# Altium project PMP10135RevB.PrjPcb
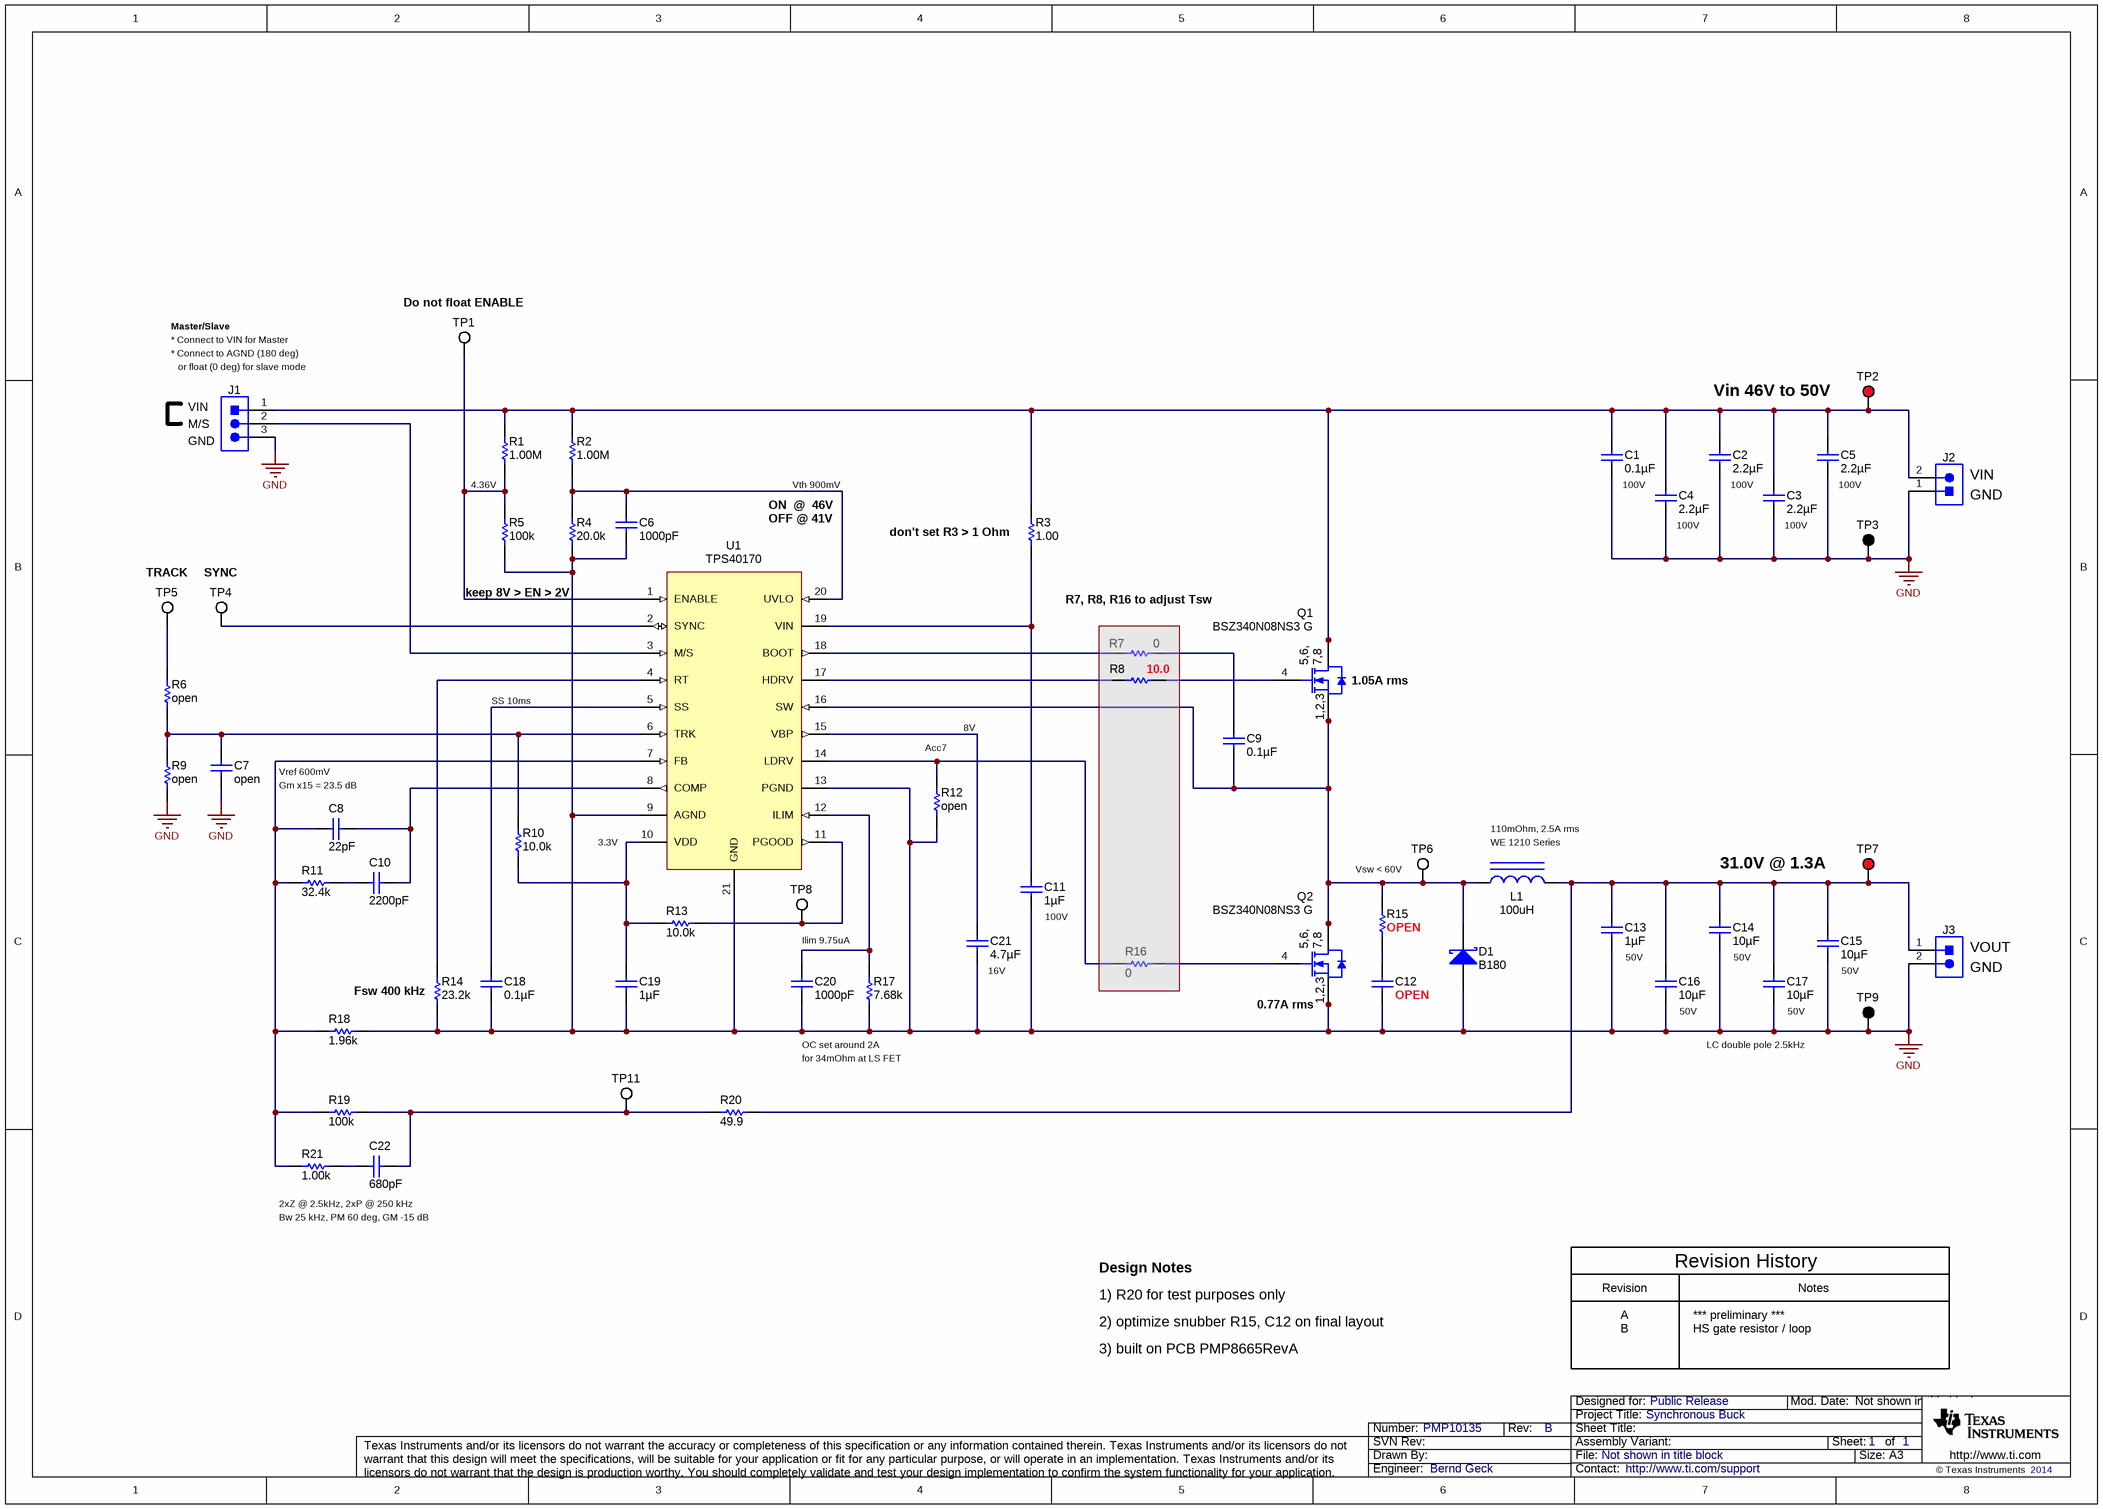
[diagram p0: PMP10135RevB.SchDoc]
CopyrightYear: 2014; PCB_Layout: B. Geck; PCB_Rev: A; PRJ_Customer: Public Release; PRJ_Engineer: Bernd Geck; PRJ_Number: PMP10135; PRJ_Title: Synchronous Buck; SCH_Rev: B; TechSupport: http://www.ti.com/support
1 sheet, 61 parts. Net scope: global (net labels, ports and power ports of the same name join across sheets).

## Sheet PMP10135RevB.SchDoc
size A3; Date: Not shown in title block; ApprovedBy: Not shown in title block; CheckedBy: Not shown in title block; Author: Not shown in title block; CompanyName: Not shown in title block; Engineer: Not shown in title block; Organization: Not shown in title block; Address1: Not shown in title block; Address2: Not shown in title block; Address3: Not shown in title block; Address4: Not shown in title block; DocumentNumber: 1; Revision: Use project parameter SCH_Rev; SheetNumber: 1; SheetTotal: 1; PageSetup: Record=PageOptions|CenterHorizontal=True|CenterVertical=True|PrintScale=0.97|XCorrection=1.00|YCorrection=1.00|PrintKind=0|BorderSize=5000000|LeftOffset=0|BottomOffset=0|Orientation=2|PaperLength=1000|PaperWidth=1000|Scale=100|PaperSource=15|PrintQuality=600|MediaType=1|DitherType=10|PaperKind=A4|PrintScaleMode=1

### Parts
C1  ValueDisplayed: 0.1µF  Value2: 100V  [0805_HV]  (hidden comment: C2012X7R2A104K)
C2  ValueDisplayed: 2.2µF  Value2: 100V  [1210]  (hidden comment: GRM32ER72A225KA35L)
C3  ValueDisplayed: 2.2µF  Value2: 100V  [1210]  (hidden comment: GRM32ER72A225KA35L)
C4  ValueDisplayed: 2.2µF  Value2: 100V  [1210]  (hidden comment: GRM32ER72A225KA35L)
C5  ValueDisplayed: 2.2µF  Value2: 100V  [1210]  (hidden comment: GRM32ER72A225KA35L)
C6  ValueDisplayed: 1000pF  [0402]  (hidden comment: GRM155R71H102KA01D)
C7  ValueDisplayed: open  [0402]  (hidden comment: GRM1535C1H101JDD5D)
C8  ValueDisplayed: 22pF  [0402]  (hidden comment: GRM1555C1H220JA01D)
C9  ValueDisplayed: 0.1µF  [0603]  (hidden comment: GRM188R71H104KA93D)
C10  ValueDisplayed: 2200pF  [0402]  (hidden comment: GRM155R71E222KA01D)
C11  ValueDisplayed: 1µF  Value2: 100V  [1206]  (hidden comment: GRM31CR72A105KA01L)
C12  ValueDisplayed: OPEN  [0805_HV]  (hidden comment: C2012X7R2A102K)
C13  ValueDisplayed: 1µF  Value2: 50V  [0805_HV]  (hidden comment: GRM21BR71H105KA12L)
C14  ValueDisplayed: 10µF  Value2: 50V  [1210]  (hidden comment: GRM32ER71H106KA12L)
C15  ValueDisplayed: 10µF  Value2: 50V  [1210]  (hidden comment: GRM32ER71H106KA12L)
C16  ValueDisplayed: 10µF  Value2: 50V  [1210]  (hidden comment: GRM32ER71H106KA12L)
C17  ValueDisplayed: 10µF  Value2: 50V  [1210]  (hidden comment: GRM32ER71H106KA12L)
C18  ValueDisplayed: 0.1µF  [0603]  (hidden comment: GRM188R71H104KA93D)
C19  ValueDisplayed: 1µF  [0603]  (hidden comment: GRM188R71E105KA12D)
C20  ValueDisplayed: 1000pF  [0603]  (hidden comment: GRM188R71H102KA01D)
C21  ValueDisplayed: 4.7µF  Value2: 16V  [0805_HV]  (hidden comment: GRM21BR71C475KA73L)
C22  ValueDisplayed: 680pF  [0402]  (hidden comment: GRM155R71H681KA01D)
D1  B180  [SMA]
J1  PEC03SAAN  [CONN_PEC03SAAN]  (value not drawn)
J2  ED555/2DS  [TERM_BLK_ED555-2DS]  (value not drawn)
J3  ED555/2DS  [TERM_BLK_ED555-2DS]  (value not drawn)
L1  100uH  [WE-PD-XXL]
Q1  BSZ340N08NS3 G  [PG-TSDSON-8]
Q2  BSZ340N08NS3 G  [PG-TSDSON-8]
R1  ValueDisplayed: 1.00M  [0805_HV]  (hidden comment: CRCW08051M00FKEA)
R2  ValueDisplayed: 1.00M  [0805_HV]  (hidden comment: CRCW08051M00FKEA)
R3  ValueDisplayed: 1.00  [0805_HV]  (hidden comment: CRCW08051R00FKEA)
R4  ValueDisplayed: 20.0k  [0402]  (hidden comment: CRCW040220K0FKED)
R5  ValueDisplayed: 100k  [0402]  (hidden comment: CRCW0402100KFKED)
R6  ValueDisplayed: open  [0402]  (hidden comment: CRCW040210K0FKED)
R7  ValueDisplayed: 0  [0603]  (hidden comment: CRCW06030000Z0EA)
R8  ValueDisplayed: 10.0  [0402]  (hidden comment: CRCW040210R0FKED)
R9  ValueDisplayed: open  [0402]  (hidden comment: CRCW040210K0FKED)
R10  ValueDisplayed: 10.0k  [0603]  (hidden comment: CRCW060310K0FKEA)
R11  ValueDisplayed: 32.4k  [0402]  (hidden comment: CRCW040232K4FKED)
R12  ValueDisplayed: open  [0603]  (hidden comment: CRCW060310K0FKEA)
R13  ValueDisplayed: 10.0k  [0603]  (hidden comment: CRCW060310K0FKEA)
R14  ValueDisplayed: 23.2k  [0402]  (hidden comment: CRCW040223K2FKED)
R15  ValueDisplayed: OPEN  [1206]  (hidden comment: CRCW120622R0JNEA)
R16  ValueDisplayed: 0  [0603]  (hidden comment: CRCW06030000Z0EA)
R17  ValueDisplayed: 7.68k  [0603]  (hidden comment: CRCW06037K68FKEA)
R18  ValueDisplayed: 1.96k  [0603]  (hidden comment: CRCW06031K96FKEA)
R19  ValueDisplayed: 100k  [0402]  (hidden comment: CRCW0402100KFKED)
R20  ValueDisplayed: 49.9  [0603]  (hidden comment: CRCW060349R9FKEA)
R21  ValueDisplayed: 1.00k  [0402]  (hidden comment: CRCW04021K00FKED)
TP1  5002  [Keystone5002]  (value not drawn)
TP2  5000  [Keystone5000]  (value not drawn)
TP3  5001  [Keystone5001]  (value not drawn)
TP4  5002  [Keystone5002]  (value not drawn)
TP5  5002  [Keystone5002]  (value not drawn)
TP6  5002  [Keystone5002]  (value not drawn)
TP7  5000  [Keystone5000]  (value not drawn)
TP8  5002  [Keystone5002]  (value not drawn)
TP9  5001  [Keystone5001]  (value not drawn)
TP11  5002  [Keystone5002]  (value not drawn)
U1  TPS40170  [RGY0020A]

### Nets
GND: C1.2 C2.2 C3.2 C4.2 C5.2 C6.2 C7.2 C11.2 C12.2 C13.2 C14.2 C15.2 C16.2 C17.2 C18.2 C19.2 C20.2 C21.2 D1.2(A) J1.3 J2.1 J3.2 Q2.1(S) Q2.2(S) Q2.3(S) R4.1 R5.1 R9.1 R12.1 R14.1 R17.1 R18.2 TP3.1 TP9.1 U1.9(AGND) U1.13(PGND) U1.21(GND)
NetC1_1: C1.1 C2.1 C3.1 C4.1 C5.1 J1.1 J2.2 Q1.5(D) Q1.6(D) Q1.7(D) Q1.8(D) Q1.9(D) R1.2 R2.2 R3.2 TP2.1
NetC6_1: C6.1 R2.1 R4.2 U1.20(UVLO)
NetC7_1: C7.1 R6.1 R9.2 R10.2 U1.6(TRK)
NetC8_1: C8.1 C10.1 U1.8(COMP)
NetC8_2: C8.2 R11.1 R18.1 R19.1 R21.1 U1.7(FB)
NetC9_1: C9.1 R7.2
NetC9_2: C9.2 D1.1(K) L1.1 Q1.1(S) Q1.2(S) Q1.3(S) Q2.5(D) Q2.6(D) Q2.7(D) Q2.8(D) Q2.9(D) R15.2 TP6.1 U1.16(SW)
NetC10_2: C10.2 R11.2
NetC11_1: C11.1 R3.1 U1.19(VIN)
NetC12_1: C12.1 R15.1
NetC13_1: C13.1 C14.1 C15.1 C16.1 C17.1 J3.1 L1.2 R20.2 TP7.1
NetC18_1: C18.1 U1.5(SS)
NetC19_1: C19.1 R10.1 R13.1 U1.10(VDD)
NetC20_1: C20.1 R17.2 U1.12(ILIM)
NetC21_1: C21.1 U1.15(VBP)
NetC22_1: C22.1 R19.2 R20.1 TP11.1
NetC22_2: C22.2 R21.2
NetJ1_2: J1.2 U1.3(M/S)
NetQ1_4: Q1.4(G) R8.2
NetQ2_4: Q2.4(G) R16.2
NetR1_1: R1.1 R5.2 TP1.1 U1.1(ENABLE)
NetR6_2: R6.2 TP5.1
NetR7_1: R7.1 U1.18(BOOT)
NetR8_1: R8.1 U1.17(HDRV)
NetR12_2: R12.2 R16.1 U1.14(LDRV)
NetR13_2: R13.2 TP8.1 U1.11(PGOOD)
NetR14_2: R14.2 U1.4(RT)
NetTP4_1: TP4.1 U1.2(SYNC)

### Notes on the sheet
- (near TP1) Do not float ENABLE
- Master/Slave
- * Connect to VIN for Master
- (near J1) * Connect to AGND (180 deg)
- (near J1) or float (0 deg) for slave mode
- (near J1) M/S
- (near J1) GND
- (near J1) VIN
- Vin 46V to 50V
- (near R1) 4.36V
- ON  @  46V
- OFF @ 41V
- Vth 900mV
- (near J2) VIN
- (near J2) GND
- TRACK
- SYNC
- keep 8V > EN > 2V
- (near R3) don't set R3 > 1 Ohm
- R7, R8, R16 to adjust Tsw
- SS 10ms
- 8V
- (near Q1) 1.05A rms
- Vref 600mV
- Gm x15 = 23.5 dB
- (near R12) Acc7
- (near U1) 3.3V
- (near L1) WE 1210 Series
- 110mOhm, 2.5A rms
- 31.0V @ 1.3A
- Vsw < 60V
- (near R14) Fsw 400 kHz
- Ilim 9.75uA
- (near J3) VOUT
- (near J3) GND
- OC set around 2A
- for 34mOhm at LS FET
- (near Q2) 0.77A rms
- LC double pole 2.5kHz
- 2xZ @ 2.5kHz, 2xP @ 250 kHz
- Bw 25 kHz, PM 60 deg, GM -15 dB
- Design Notes
- Revision History
- 1) R20 for test purposes only
- 2) optimize snubber R15, C12 on final layout
- Revision
- A
- B
- *** preliminary ***
- HS gate resistor / loop
- Notes
- 3) built on PCB PMP8665RevA

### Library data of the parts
C1 = C2012X7R2A104K: CAP, CERM, 0.1 µF, 100 V, +/- 10%, X7R, 0805; Manufacturer: TDK; Polarized: N; CompType: Capacitor; Value: 0.1uF; U/M: EA; Cap_F: 0.0000001; Tolerance_%: 10; ESR_ohm: 0.0158; Value1: 0.0158 ohm; VDC_V: 100; TaMin_C: -55; TaMax_C: 125; Cap_Case: 0805
C2-C5 = GRM32ER72A225KA35L: CAP, CERM, 2.2 µF, 100 V, +/- 10%, X7R, 1210; Manufacturer: MuRata; Polarized: N; CompType: Capacitor; Value: 2.2uF; U/M: EA; Cap_F: 0.0000022; Tolerance_%: 10; ESR_ohm: 0.007; Value1: 0.007 ohm; VDC_V: 100; IRMS_A: 4.4; TaMin_C: -55; TaMax_C: 125
C6 = GRM155R71H102KA01D: CAP, CERM, 1000 pF, 50 V, +/- 10%, X7R, 0402; Manufacturer: MuRata; Polarized: N; CompType: Capacitor; Value: 1000pF; U/M: EA; Cap_F: 0.000000001; Tolerance_%: 10; Value1: Unknown; VDC_V: 50; Value2: 50V; TaMin_C: -55; TaMax_C: 125
C7 = GRM1535C1H101JDD5D: CAP, CERM, 100 pF, 50 V, +/- 5%, C0G/NP0, 0402; Manufacturer: MuRata; Polarized: N; CompType: Capacitor; Value: 100pF; U/M: EA; Cap_F: 0.0000000001; Tolerance_%: 5; Value1: Unknown; VDC_V: 50; Value2: 50V; TaMin_C: -55; TaMax_C: 125
C8 = GRM1555C1H220JA01D: CAP, CERM, 22 pF, 50 V, +/- 5%, C0G/NP0, 0402; Manufacturer: MuRata; Polarized: N; CompType: Capacitor; Value: 22pF; U/M: EA; Cap_F: 0.000000000022; Tolerance_%: 5; Value1: Unknown; VDC_V: 50; Value2: 50V; TaMin_C: -55; TaMax_C: 125
C9 C18 = GRM188R71H104KA93D: CAP, CERM, 0.1 µF, 50 V, +/- 10%, X7R, 0603; Manufacturer: MuRata; Polarized: N; CompType: Capacitor; Value: 0.1uF; U/M: EA; Cap_F: 0.0000001; Tolerance_%: 10; Value1: Unknown; VDC_V: 50; Value2: 50V; TaMin_C: -55; TaMax_C: 125
C10 = GRM155R71E222KA01D: CAP, CERM, 2200 pF, 25 V, +/- 10%, X7R, 0402; Manufacturer: MuRata; Polarized: N; CompType: Capacitor; Value: 2200pF; U/M: EA; Cap_F: 0.0000000022; Tolerance_%: 10; Value1: Unknown; VDC_V: 25; Value2: 25V; TaMin_C: -55; TaMax_C: 125
C11 = GRM31CR72A105KA01L: CAP, CERM, 1 µF, 100 V, +/- 10%, X7R, 1206; Manufacturer: MuRata; Polarized: N; CompType: Capacitor; Value: 1uF; U/M: EA; Cap_F: 0.000001; Tolerance_%: 10; Value1: Unknown; VDC_V: 100; TaMin_C: -55; TaMax_C: 125; Cap_Case: 2220
C12 = C2012X7R2A102K: CAP, CERM, 1000 pF, 100 V, +/- 10%, X7R, 0805; Manufacturer: TDK; Polarized: N; CompType: Capacitor; Value: 1000pF; U/M: EA; Cap_F: 0.000000001; Tolerance_%: 10; ESR_ohm: 0.281; Value1: 0.281 ohm; VDC_V: 100; Value2: 100V; TaMin_C: -55; TaMax_C: 125; Cap_Case: 0805
C13 = GRM21BR71H105KA12L: CAP, CERM, 1 µF, 50 V, +/- 10%, X7R, 0805; Manufacturer: MuRata; Polarized: N; CompType: Capacitor; Value: 1uF; U/M: EA; Cap_F: 0.000001; Tolerance_%: 10; Value1: Unknown; VDC_V: 50; TaMin_C: -55; TaMax_C: 125; Cap_Case: 0805
C14-C17 = GRM32ER71H106KA12L: CAP, CERM, 10 µF, 50 V, +/- 10%, X7R, 1210; Manufacturer: MuRata; Polarized: N; CompType: Capacitor; Value: 10uF; U/M: EA; Cap_F: 0.00001; Tolerance_%: 10; Value1: Unknown; VDC_V: 50; TaMin_C: -55; TaMax_C: 125
C19 = GRM188R71E105KA12D: CAP, CERM, 1 µF, 25 V, +/- 10%, X7R, 0603; Manufacturer: MuRata; Polarized: N; CompType: Capacitor; Value: 1uF; U/M: EA; Cap_F: 0.000001; Tolerance_%: 10; Value1: Unknown; VDC_V: 25; Value2: 25V; TaMin_C: -55; TaMax_C: 125
C20 = GRM188R71H102KA01D: CAP, CERM, 1000 pF, 50 V, +/- 10%, X7R, 0603; Manufacturer: MuRata; Polarized: N; CompType: Capacitor; Value: 1000pF; U/M: EA; Cap_F: 0.000000001; Tolerance_%: 10; Value1: Unknown; VDC_V: 50; Value2: 50V; TaMin_C: -55; TaMax_C: 125
C21 = GRM21BR71C475KA73L: CAP, CERM, 4.7 µF, 16 V, +/- 10%, X7R, 0805; Manufacturer: MuRata; Polarized: N; CompType: Capacitor; Value: 4.7uF; U/M: EA; Cap_F: 0.0000047; Tolerance_%: 10; ESR_ohm: 0.006; Value1: 0.006 ohm; VDC_V: 16; TaMin_C: -55; TaMax_C: 125; Cap_Case: 0805
C22 = GRM155R71H681KA01D: CAP, CERM, 680 pF, 50 V, +/- 10%, X7R, 0402; Manufacturer: MuRata; Polarized: N; CompType: Capacitor; Value: 680pF; U/M: EA; Cap_F: 0.00000000068; Tolerance_%: 10; Value1: Unknown; VDC_V: 50; Value2: 50V; TaMin_C: -55; TaMax_C: 125
D1 = B180-13-F: Diode, Schottky, 80 V, 1 A, SMA; Manufacturer: Diodes Inc.; U/M: EA; Vf_V: 0.79; Value: 80V; Value1: 1A; Value2: 0.79V; Io_A: 1; Vr_V: 80; TJmax_C: 150; RJC_CperW: 25
J1 = PEC03SAAN: Header, 100mil, 3x1, Tin, TH; Manufacturer: Sullins Connector Solutions; SymbolCreator: a0799628; U/M: EA
J2 J3 = ED555/2DS: Terminal Block, 6A, 3.5mm Pitch, 2-Pos, TH; Manufacturer: On-Shore Technology; SymbolCreator: a0412235; CompType: Connector; U/M: EA
L1 = 7447709101: Inductor, Shielded Drum Core, Ferrite, 100 µH, 2.5 A, 0.1 ohm, SMD; Manufacturer: Wurth Elektronik eiSos; Ind_H: 100.0E-6; ValueDisplayed: 100µH; Imax_A: 2.5; Irms: 2.5A @ 40C rise; Isat: 3.1A @ 10% inductance drop; DCR_ohm: 0.1; Value1: 0.1 ohm; Value2: 2.5A
Q1 Q2 = BSZ123N08NS3 G: MOSFET, N-CH, 80 V, 23 A, PG-TSDSON-8; Manufacturer: Infineon Technologies; Alternate Manufacturer: None; U/M: EA; ChType: N; Value: 80V; VdsMax_V: 80; Value1: 0.038 ohm; Value2: 6.8 nC; QgTyp_nC: 6.8; Vgs_V: 20; IdsMax_A: 23
R1 R2 = CRCW08051M00FKEA: RES, 1.00 M, 1%, 0.125 W, 0805; Manufacturer: Vishay-Dale; CompType: Resistor; Value: 1.00Meg; Res_ohm: 1000000; Value_Code: 1M00; Tolerance_%: 1; Power_W: 0.125; Value2: 0.125W; VDC_V: 150; TempCo: 100 ppm/C; EIA_Code: E96; U/M: EA
R3 = CRCW08051R00FKEA: RES, 1.00, 1%, 0.125 W, 0805; Manufacturer: Vishay-Dale; CompType: Resistor; Value: 1.00; Res_ohm: 1; Value_Code: 1R00; Power_W: 0.125; Value2: 0.125W; VDC_V: 150; TempCo: 100 ppm/C; EIA_Code: E96; U/M: EA
R4 = CRCW040220K0FKED: RES, 20.0 k, 1%, 0.063 W, 0402; Manufacturer: Vishay-Dale; CompType: Resistor; Value: 20.0k; Res_ohm: 20000; Value_Code: 20k0; Tolerance_%: 1; Power_W: 0.063; Value2: 0.063W; VDC_V: 50; TempCo: 100 ppm/C; EIA_Code: E96; U/M: EA
R5 R19 = CRCW0402100KFKED: RES, 100 k, 1%, 0.063 W, 0402; Manufacturer: Vishay-Dale; CompType: Resistor; Value: 100k; Res_ohm: 100000; Tolerance_%: 1; Power_W: 0.063; Value2: 0.063W; VDC_V: 50; TempCo: 100 ppm/C; EIA_Code: E96; U/M: EA
R6 R9 = CRCW040210K0FKED: RES, 10.0 k, 1%, 0.063 W, 0402; Manufacturer: Vishay-Dale; CompType: Resistor; Value: 10.0k; Res_ohm: 10000; Value_Code: 10k0; Tolerance_%: 1; Power_W: 0.063; Value2: 0.063W; VDC_V: 50; TempCo: 100 ppm/C; EIA_Code: E96; U/M: EA
R7 R16 = CRCW06030000Z0EA: RES, 0, 5%, 0.1 W, 0603; Manufacturer: Vishay-Dale; CompType: Resistor; Value: 0; Value_Code: 0000; Tolerance_%: 5; Power_W: 0.1; Value2: 0.1W; VDC_V: 75; TempCo: 200 ppm/C; EIA_Code: E24; U/M: EA
R8 = CRCW040210R0FKED: RES, 10.0, 1%, 0.063 W, 0402; Manufacturer: Vishay-Dale; CompType: Resistor; Value: 10.0; Res_ohm: 10; Value_Code: 10R0; Tolerance_%: 1; Power_W: 0.063; Value2: 0.063W; VDC_V: 50; TempCo: 100 ppm/C; EIA_Code: E96; U/M: EA
R10 R12 R13 = CRCW060310K0FKEA: RES, 10.0 k, 1%, 0.1 W, 0603; Manufacturer: Vishay-Dale; CompType: Resistor; Value: 10.0k; Res_ohm: 10000; Value_Code: 10k0; Tolerance_%: 1; Power_W: 0.1; Value2: 0.1W; VDC_V: 75; TempCo: 100 ppm/C; EIA_Code: E96; U/M: EA
R11 = CRCW040232K4FKED: RES, 32.4 k, 1%, 0.063 W, 0402; Manufacturer: Vishay-Dale; CompType: Resistor; Value: 32.4k; Res_ohm: 32400; Value_Code: 32k4; Tolerance_%: 1; Power_W: 0.063; Value2: 0.063W; VDC_V: 50; TempCo: 100 ppm/C; EIA_Code: E96; U/M: EA
R14 = CRCW040223K2FKED: RES, 23.2 k, 1%, 0.063 W, 0402; Manufacturer: Vishay-Dale; CompType: Resistor; Value: 23.2k; Res_ohm: 23200; Value_Code: 23k2; Tolerance_%: 1; Power_W: 0.063; Value2: 0.063W; VDC_V: 50; TempCo: 100 ppm/C; EIA_Code: E96; U/M: EA
R15 = CRCW120622R0JNEA: RES, 22, 5%, 0.25 W, 1206; Manufacturer: Vishay-Dale; CompType: Resistor; Value: 22; Value_Code: 22R0; Tolerance_%: 5; Power_W: 0.25; Value2: 0.25W; VDC_V: 200; TempCo: 200 ppm/C; EIA_Code: E24; U/M: EA
R17 = CRCW06037K68FKEA: RES, 7.68 k, 1%, 0.1 W, 0603; Manufacturer: Vishay-Dale; CompType: Resistor; Value: 7.68k; Res_ohm: 7680; Value_Code: 7k68; Tolerance_%: 1; Power_W: 0.1; Value2: 0.1W; VDC_V: 75; TempCo: 100 ppm/C; EIA_Code: E96; U/M: EA
R18 = CRCW06031K96FKEA: RES, 1.96 k, 1%, 0.1 W, 0603; Manufacturer: Vishay-Dale; CompType: Resistor; Value: 1.96k; Res_ohm: 1960; Value_Code: 1k96; Tolerance_%: 1; Power_W: 0.1; Value2: 0.1W; VDC_V: 75; TempCo: 100 ppm/C; EIA_Code: E96; U/M: EA
R20 = CRCW060349R9FKEA: RES, 49.9, 1%, 0.1 W, 0603; Manufacturer: Vishay-Dale; CompType: Resistor; Value: 49.9; Value_Code: 49R9; Tolerance_%: 1; Power_W: 0.1; Value2: 0.1W; VDC_V: 75; TempCo: 100 ppm/C; EIA_Code: E96; U/M: EA
R21 = CRCW04021K00FKED: RES, 1.00 k, 1%, 0.063 W, 0402; Manufacturer: Vishay-Dale; CompType: Resistor; Value: 1.00k; Res_ohm: 1000; Value_Code: 1k00; Tolerance_%: 1; Power_W: 0.063; Value2: 0.063W; VDC_V: 50; TempCo: 100 ppm/C; EIA_Code: E96; U/M: EA
TP1 TP4-TP6 TP8 TP11 = 5002: Test Point, Miniature, White, TH; Manufacturer: Keystone; CompType: Test Point Loop; U/M: EA
TP2 TP7 = 5000: Test Point, Miniature, Red, TH; Manufacturer: Keystone; CompType: Test Point Loop; U/M: EA
TP3 TP9 = 5001: Test Point, Miniature, Black, TH; Manufacturer: Keystone; CompType: Test Point Loop; U/M: EA
U1 = TPS40170RGY: 4.5-v to 60-v wide-input synchronous PWM buck controller, RGY0020A; Manufacturer: Texas Instruments; SymbolCreator: a0412235/PADS; CompType: IC; U/M: EA

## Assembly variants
001: all parts fitted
